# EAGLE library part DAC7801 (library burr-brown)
Dual Monolithic CMOS 12-Bit DAC Multiplying
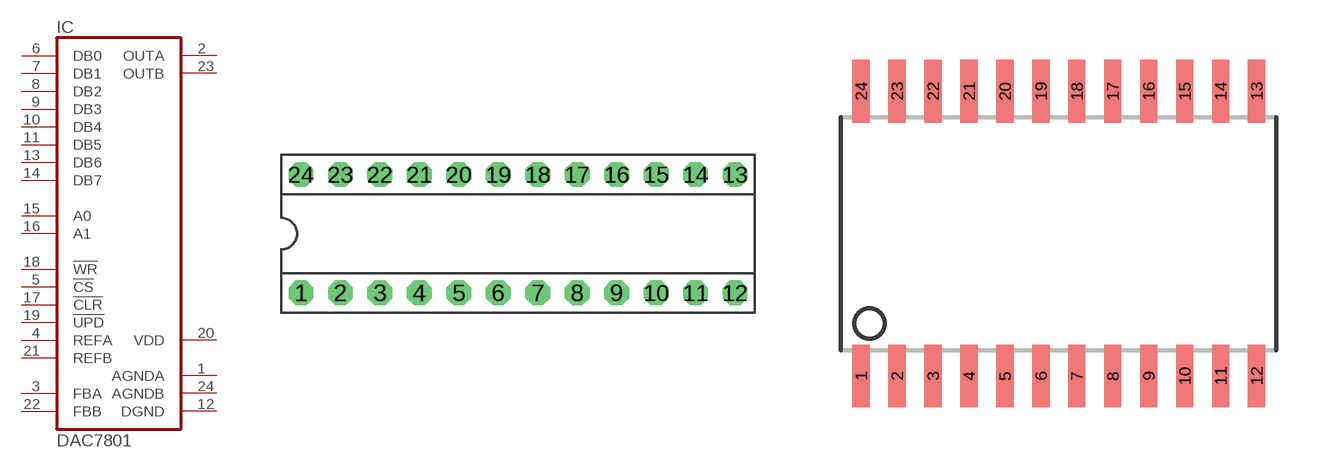
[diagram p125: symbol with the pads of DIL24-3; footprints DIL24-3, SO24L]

Designator prefix IC

## DAC7801P (MF: TEXAS INSTRUMENT CONNECTORS; MPN: DAC7801KP; OC_FARNELL: 1460235; OC_NEWARK: 14M8160)  [DIL24-3]
1  AGNDA  pwr
2  OUTA  out
3  FBA  pas
4  REFA  in
5  !CS  in
6  DB0  in
7  DB1  in
8  DB2  in
9  DB3  in
10  DB4  in
11  DB5  in
12  DGND  pwr
13  DB6  in
14  DB7  in
15  A0  in
16  A1  in
17  !CLR  in
18  !WR  in
19  !UPD  in
20  VDD  pwr
21  REFB  in
22  FBB  pas
23  OUTB  out
24  AGNDB  pwr

## DAC7801U (MPN: DAC7801KU; OC_FARNELL: 1460236; OC_NEWARK: 61M5748)  [SO24L]
Pads as for DIL24-3

## Footprint DIL24-3 (pad centres in mm)
Dual In Line 0.3 inch
drill 0.813 pad 1.6 octagon: 1 -13.97,-3.81; 2 -11.43,-3.81; 3 -8.89,-3.81; 4 -6.35,-3.81; 5 -3.81,-3.81; 6 -1.27,-3.81; 7 1.27,-3.81; 8 3.81,-3.81; 9 6.35,-3.81; 10 8.89,-3.81; 11 11.43,-3.81; 12 13.97,-3.81; 13 13.97,3.81; 14 11.43,3.81; 15 8.89,3.81; 16 6.35,3.81; 17 3.81,3.81; 18 1.27,3.81; 19 -1.27,3.81; 20 -3.81,3.81; 21 -6.35,3.81; 22 -8.89,3.81; 23 -11.43,3.81; 24 -13.97,3.81

## Footprint SO24L (pad centres in mm)
Small Outline Package, large
smd 0.61 x 2.21: 1 -6.985,-5.029; 2 -5.715,-5.029; 3 -4.445,-5.029; 4 -3.175,-5.029; 5 -1.905,-5.029; 6 -0.635,-5.029; 7 0.635,-5.029; 8 1.905,-5.029; 9 3.175,-5.029; 10 4.445,-5.029; 11 5.715,-5.029; 12 6.985,-5.029; 13 6.985,5.029; 14 5.715,5.029; 15 4.445,5.029; 16 3.175,5.029; 17 1.905,5.029; 18 0.635,5.029; 19 -0.635,5.029; 20 -1.905,5.029; 21 -3.175,5.029; 22 -4.445,5.029; 23 -5.715,5.029; 24 -6.985,5.029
